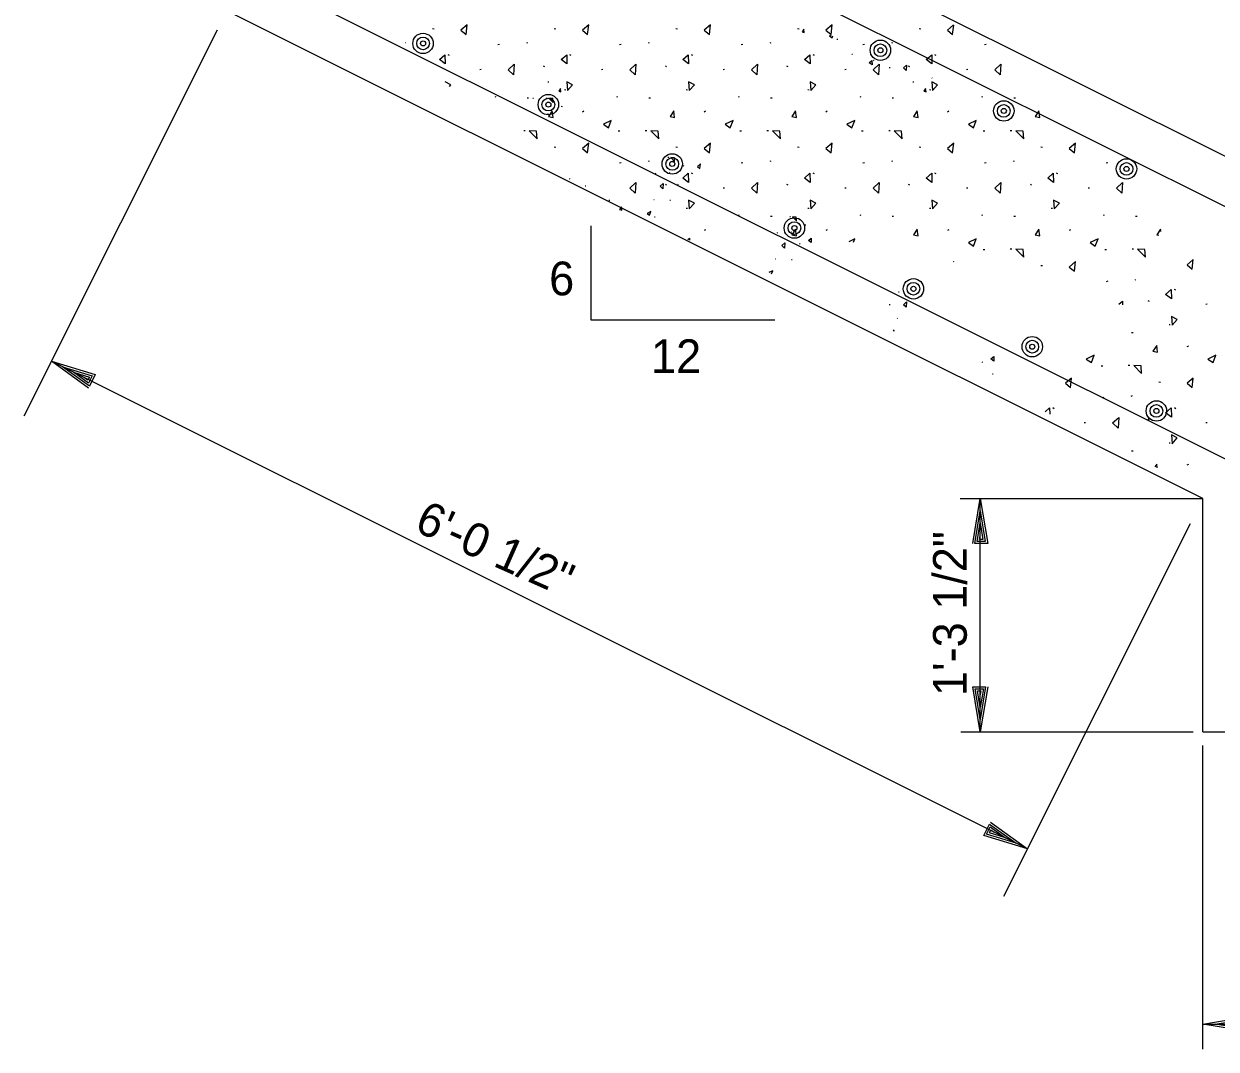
# Model space of a CAD drawing. Extents: x 6 to 106, y 3 to 74.
# Drawn here: x 75.94 to 89.14, y 24.57 to 35.93 of the extents above; entities that cross this region are included whole.
import ezdxf

# ---------------------------------------------------------------- set-up
doc = ezdxf.new("R2010")
doc.units = 0
for name, color, linetype in [('Level 22', 7, 'Continuous'), ('Level 25', 7, 'Continuous'), ('Level 44', 7, 'Continuous'), ('Level 50', 7, 'Continuous')]:
    doc.layers.add(name, color=color, linetype=linetype)

msp = doc.modelspace()

# ---------------------------------------------------------------- linework, layer by layer
at = {"layer": 'Level 22'}
for p, q in [((92.955, 32.603), (79.753, 39.204)), ((94.265, 31.389), (80.275, 38.384)), ((88.991, 30.672), (78.188, 36.074)), ((90.607, 30.423), (79.157, 36.148)), ((78.081, 35.86), (75.942, 31.582)), ((82.222, 32.645), (82.222, 33.692)), ((84.255, 32.645), (82.222, 32.645)), ((87.05, 26.791), (76.247, 32.192)), ((86.305, 30.672), (88.991, 30.672)), ((88.849, 30.389), (86.786, 26.264)), ((86.311, 28.086), (88.883, 28.086)), ((88.991, 24.85), (96.991, 24.85))]:
    msp.add_line(p, q, dxfattribs=at)
at = {"layer": 'Level 25'}
for p, q in [((86.527, 28.086), (86.527, 30.672)), ((88.991, 28.086), (88.991, 30.672)), ((88.991, 28.086), (96.991, 28.086)), ((88.991, 24.572), (88.991, 27.935))]:
    msp.add_line(p, q, dxfattribs=at)
at = {"layer": 'Level 44'}
for p, q in [((80.483, 35.87), (80.466, 35.873)), ((81.83, 35.87), (81.813, 35.873)), ((83.177, 35.87), (83.159, 35.873)), ((84.523, 35.87), (84.506, 35.873)), ((85.87, 35.87), (85.853, 35.873)), ((80.17, 35.719), (80.165, 35.717)), ((81.206, 35.701), (81.188, 35.696)), ((81.517, 35.719), (81.504, 35.714)), ((82.553, 35.701), (82.535, 35.696)), ((82.864, 35.719), (82.851, 35.714)), ((83.9, 35.701), (83.882, 35.696)), ((84.21, 35.719), (84.197, 35.714)), ((84.95, 35.756), (84.941, 35.756)), ((85.246, 35.701), (85.228, 35.696)), ((85.557, 35.719), (85.544, 35.714)), ((86.593, 35.701), (86.575, 35.696)), ((80.653, 35.578), (80.638, 35.587)), ((82, 35.578), (81.985, 35.587)), ((83.346, 35.578), (83.331, 35.587)), ((84.693, 35.578), (84.678, 35.587)), ((85.113, 35.59), (85.106, 35.588)), ((85.354, 35.52), (85.347, 35.524)), ((86.04, 35.578), (86.025, 35.587)), ((81.002, 35.422), (80.988, 35.421)), ((81.709, 35.454), (81.695, 35.461)), ((82.349, 35.422), (82.334, 35.421)), ((83.056, 35.454), (83.042, 35.461)), ((83.696, 35.422), (83.681, 35.421)), ((84.403, 35.454), (84.388, 35.461)), ((85.042, 35.422), (85.028, 35.421)), ((85.529, 35.442), (85.521, 35.441)), ((85.749, 35.454), (85.735, 35.461)), ((86.389, 35.422), (86.374, 35.421)), ((81.752, 35.284), (81.743, 35.284)), ((85.792, 35.284), (85.783, 35.284)), ((85.997, 35.328), (85.991, 35.329)), ((81.171, 35.117), (81.157, 35.119)), ((81.529, 35.106), (81.511, 35.106)), ((81.733, 35.103), (81.724, 35.103)), ((81.94, 35.195), (81.926, 35.196)), ((82.517, 35.117), (82.504, 35.119)), ((82.876, 35.106), (82.858, 35.106)), ((83.286, 35.195), (83.273, 35.196)), ((83.864, 35.117), (83.851, 35.119)), ((84.223, 35.106), (84.205, 35.106)), ((84.633, 35.195), (84.62, 35.196)), ((85.211, 35.117), (85.197, 35.119)), ((85.569, 35.106), (85.551, 35.106)), ((85.98, 35.195), (85.966, 35.196)), ((86.557, 35.117), (86.544, 35.119)), ((86.916, 35.106), (86.898, 35.106)), ((81.584, 35.1), (81.575, 35.1)), ((81.903, 35.01), (81.894, 35.012)), ((81.746, 34.935), (81.74, 34.932)), ((82.14, 34.96), (82.124, 34.952)), ((83.487, 34.96), (83.471, 34.952)), ((84.833, 34.96), (84.817, 34.952)), ((86.18, 34.96), (86.164, 34.952)), ((81.491, 34.745), (81.474, 34.745)), ((82.539, 34.739), (82.521, 34.739)), ((82.837, 34.745), (82.82, 34.745)), ((83.885, 34.739), (83.867, 34.739)), ((84.184, 34.745), (84.167, 34.745)), ((85.232, 34.739), (85.214, 34.739)), ((85.531, 34.745), (85.514, 34.745)), ((86.579, 34.739), (86.561, 34.739)), ((86.877, 34.745), (86.86, 34.745)), ((81.83, 34.559), (81.813, 34.562)), ((83.08, 34.447), (83.071, 34.447)), ((83.177, 34.559), (83.159, 34.562)), ((84.523, 34.559), (84.506, 34.562)), ((85.87, 34.559), (85.853, 34.562)), ((87.217, 34.559), (87.199, 34.562)), ((82.553, 34.39), (82.535, 34.385)), ((82.864, 34.408), (82.851, 34.403)), ((83.249, 34.354), (83.241, 34.356)), ((83.9, 34.39), (83.882, 34.385)), ((84.21, 34.408), (84.197, 34.403)), ((85.246, 34.39), (85.228, 34.385)), ((85.557, 34.408), (85.544, 34.403)), ((86.593, 34.39), (86.575, 34.385)), ((86.904, 34.408), (86.891, 34.403)), ((87.94, 34.39), (87.922, 34.385)), ((81.987, 34.208), (81.98, 34.213)), ((82.937, 34.27), (82.928, 34.267)), ((83.093, 34.279), (83.086, 34.276)), ((83.346, 34.266), (83.331, 34.275)), ((84.693, 34.266), (84.678, 34.275)), ((86.04, 34.266), (86.025, 34.275)), ((87.386, 34.266), (87.371, 34.275)), ((82.162, 34.13), (82.155, 34.129)), ((83.056, 34.142), (83.042, 34.149)), ((83.189, 34.146), (83.182, 34.149)), ((83.696, 34.11), (83.681, 34.109)), ((84.403, 34.142), (84.388, 34.149)), ((85.042, 34.11), (85.028, 34.109)), ((85.749, 34.142), (85.735, 34.149)), ((86.389, 34.11), (86.374, 34.109)), ((87.096, 34.142), (87.082, 34.149)), ((87.736, 34.11), (87.721, 34.109)), ((82.426, 33.972), (82.417, 33.972)), ((82.92, 33.978), (82.913, 33.979)), ((83.099, 33.972), (83.09, 33.972)), ((82.93, 33.788), (82.921, 33.788)), ((83.286, 33.883), (83.273, 33.884)), ((83.864, 33.805), (83.851, 33.808)), ((84.223, 33.794), (84.205, 33.794)), ((84.426, 33.792), (84.418, 33.792)), ((84.633, 33.883), (84.62, 33.884)), ((85.211, 33.805), (85.197, 33.808)), ((85.569, 33.794), (85.551, 33.794)), ((85.98, 33.883), (85.966, 33.884)), ((86.557, 33.805), (86.544, 33.808)), ((86.916, 33.794), (86.898, 33.794)), ((87.326, 33.883), (87.313, 33.884)), ((87.904, 33.805), (87.891, 33.808)), ((88.263, 33.794), (88.245, 33.794)), ((84.596, 33.698), (84.587, 33.7)), ((83.093, 33.623), (83.091, 33.622)), ((83.487, 33.648), (83.473, 33.641)), ((84.284, 33.614), (84.275, 33.611)), ((84.439, 33.623), (84.433, 33.62)), ((84.833, 33.648), (84.817, 33.64)), ((86.18, 33.648), (86.164, 33.64)), ((87.527, 33.648), (87.511, 33.64)), ((84.536, 33.49), (84.528, 33.494)), ((86.579, 33.427), (86.561, 33.427)), ((86.877, 33.433), (86.86, 33.433)), ((87.925, 33.427), (87.907, 33.427)), ((88.224, 33.433), (88.207, 33.433)), ((84.266, 33.322), (84.26, 33.323)), ((84.446, 33.316), (84.437, 33.316)), ((87.217, 33.247), (87.199, 33.25)), ((87.94, 33.078), (87.922, 33.073)), ((88.246, 33.094), (88.237, 33.091)), ((85.631, 32.958), (85.622, 32.956)), ((85.786, 32.967), (85.78, 32.965)), ((88.4, 32.854), (88.386, 32.86)), ((88.691, 32.978), (88.676, 32.987)), ((85.529, 32.818), (85.521, 32.818)), ((89.04, 32.822), (89.025, 32.82)), ((85.613, 32.666), (85.606, 32.667)), ((88.631, 32.595), (88.617, 32.596)), ((88.22, 32.505), (88.202, 32.505)), ((88.831, 32.36), (88.815, 32.352)), ((86.556, 32.179), (86.548, 32.182)), ((87.883, 32.138), (87.865, 32.138)), ((88.182, 32.145), (88.165, 32.145)), ((86.671, 32.049), (86.664, 32.05)), ((88.521, 31.958), (88.504, 31.961)), ((88.208, 31.807), (88.195, 31.802)), ((87.344, 31.666), (87.329, 31.675)), ((87.897, 31.789), (87.879, 31.784)), ((88.691, 31.666), (88.676, 31.675)), ((88.4, 31.542), (88.386, 31.549)), ((87.693, 31.51), (87.679, 31.509)), ((89.04, 31.51), (89.025, 31.509)), ((88.631, 31.283), (88.617, 31.284)), ((88.22, 31.194), (88.202, 31.194)), ((88.831, 31.048), (88.815, 31.04))]:
    msp.add_line(p, q, dxfattribs=at)
for points in [[(80.847, 35.918), (80.779, 35.859), (80.836, 35.811)], [(82.194, 35.918), (82.126, 35.859), (82.182, 35.811)], [(83.541, 35.918), (83.472, 35.859), (83.529, 35.811)], [(84.887, 35.918), (84.819, 35.859), (84.876, 35.811)], [(84.58, 35.833), (84.576, 35.869), (84.555, 35.839)], [(80.606, 35.484), (80.542, 35.532), (80.603, 35.586)], [(81.952, 35.484), (81.888, 35.532), (81.95, 35.586)], [(83.299, 35.484), (83.235, 35.532), (83.296, 35.586)], [(84.646, 35.484), (84.582, 35.532), (84.643, 35.586)], [(85.33, 35.473), (85.298, 35.497), (85.329, 35.524)], [(85.992, 35.484), (85.928, 35.532), (85.99, 35.586)], [(81.363, 35.363), (81.301, 35.42), (81.369, 35.481)], [(82.709, 35.363), (82.648, 35.42), (82.716, 35.481)], [(84.056, 35.363), (83.994, 35.42), (84.063, 35.481)], [(85.403, 35.363), (85.341, 35.42), (85.409, 35.481)], [(85.709, 35.412), (85.678, 35.441), (85.712, 35.471)], [(86.749, 35.363), (86.688, 35.42), (86.756, 35.481)], [(81.959, 35.19), (82.016, 35.254), (81.952, 35.288)], [(83.306, 35.19), (83.363, 35.254), (83.299, 35.288)], [(84.652, 35.19), (84.709, 35.254), (84.646, 35.288)], [(85.999, 35.19), (86.056, 35.254), (85.992, 35.288)], [(81.795, 35.101), (81.755, 35.103), (81.799, 35.059)], [(81.887, 35.177), (81.882, 35.213), (81.862, 35.183)], [(85.927, 35.177), (85.922, 35.213), (85.902, 35.183)], [(81.799, 34.892), (81.789, 34.965), (81.748, 34.904)], [(82.413, 34.778), (82.444, 34.859), (82.356, 34.816)], [(83.145, 34.892), (83.136, 34.965), (83.095, 34.904)], [(83.759, 34.778), (83.791, 34.859), (83.703, 34.816)], [(84.492, 34.892), (84.483, 34.965), (84.442, 34.904)], [(85.106, 34.778), (85.138, 34.859), (85.049, 34.816)], [(85.839, 34.892), (85.829, 34.965), (85.788, 34.904)], [(86.453, 34.778), (86.484, 34.859), (86.396, 34.816)], [(87.185, 34.892), (87.176, 34.965), (87.135, 34.904)], [(81.616, 34.741), (81.536, 34.745), (81.622, 34.656)], [(82.962, 34.741), (82.882, 34.745), (82.969, 34.656)], [(84.309, 34.741), (84.229, 34.745), (84.316, 34.656)], [(85.656, 34.741), (85.576, 34.745), (85.662, 34.656)], [(87.002, 34.741), (86.922, 34.745), (87.009, 34.656)], [(82.194, 34.607), (82.126, 34.547), (82.182, 34.499)], [(83.541, 34.607), (83.472, 34.547), (83.529, 34.499)], [(84.887, 34.607), (84.819, 34.547), (84.876, 34.499)], [(86.234, 34.607), (86.166, 34.547), (86.222, 34.499)], [(87.581, 34.607), (87.512, 34.547), (87.569, 34.499)], [(83.142, 34.445), (83.102, 34.447), (83.145, 34.403)], [(83.431, 34.378), (83.397, 34.348), (83.425, 34.325)], [(83.299, 34.172), (83.235, 34.22), (83.296, 34.275)], [(84.646, 34.172), (84.582, 34.22), (84.643, 34.275)], [(85.992, 34.172), (85.928, 34.22), (85.99, 34.275)], [(87.339, 34.172), (87.275, 34.22), (87.336, 34.275)], [(82.709, 34.052), (82.648, 34.109), (82.716, 34.17)], [(83.016, 34.101), (82.985, 34.129), (83.019, 34.16)], [(84.056, 34.052), (83.994, 34.109), (84.063, 34.17)], [(85.403, 34.052), (85.341, 34.109), (85.409, 34.17)], [(86.749, 34.052), (86.688, 34.109), (86.756, 34.17)], [(88.096, 34.052), (88.034, 34.109), (88.103, 34.17)], [(83.306, 33.879), (83.363, 33.943), (83.299, 33.977)], [(84.652, 33.879), (84.709, 33.943), (84.646, 33.977)], [(85.999, 33.879), (86.056, 33.943), (85.992, 33.977)], [(87.346, 33.879), (87.403, 33.943), (87.339, 33.977)], [(82.56, 33.865), (82.556, 33.902), (82.535, 33.871)], [(82.867, 33.808), (82.883, 33.849), (82.839, 33.827)], [(84.489, 33.789), (84.449, 33.792), (84.492, 33.747)], [(84.492, 33.581), (84.483, 33.654), (84.442, 33.593)], [(85.839, 33.581), (85.829, 33.654), (85.788, 33.593)], [(87.185, 33.581), (87.176, 33.654), (87.135, 33.593)], [(84.657, 33.505), (84.625, 33.529), (84.656, 33.556)], [(86.453, 33.466), (86.484, 33.548), (86.396, 33.505)], [(87.799, 33.466), (87.831, 33.548), (87.743, 33.505)], [(84.362, 33.445), (84.331, 33.473), (84.366, 33.504)], [(87.002, 33.429), (86.922, 33.433), (87.009, 33.345)], [(88.349, 33.429), (88.269, 33.433), (88.356, 33.345)], [(87.581, 33.295), (87.512, 33.235), (87.569, 33.188)], [(88.885, 33.318), (88.817, 33.258), (88.873, 33.211)], [(88.643, 32.883), (88.579, 32.932), (88.641, 32.986)], [(85.709, 32.789), (85.678, 32.818), (85.712, 32.848)], [(88.65, 32.59), (88.707, 32.654), (88.643, 32.688)], [(88.49, 32.292), (88.48, 32.365), (88.439, 32.304)], [(86.677, 32.193), (86.645, 32.218), (86.676, 32.245)], [(87.757, 32.177), (87.789, 32.259), (87.7, 32.216)], [(89.104, 32.177), (89.135, 32.259), (89.047, 32.216)], [(88.307, 32.14), (88.227, 32.145), (88.313, 32.056)], [(87.538, 32.006), (87.47, 31.947), (87.527, 31.899)], [(88.885, 32.006), (88.817, 31.947), (88.873, 31.899)], [(88.643, 31.572), (88.579, 31.62), (88.641, 31.674)], [(88.054, 31.451), (87.992, 31.508), (88.06, 31.569)], [(88.65, 31.278), (88.707, 31.342), (88.643, 31.376)]]:
    msp.add_lwpolyline(points, close=True, dxfattribs=at)
for points in [[(86.232, 35.916), (86.166, 35.859), (86.222, 35.811), (86.234, 35.915)], [(84.877, 35.804), (84.859, 35.795), (84.887, 35.775)], [(84.887, 35.775), (84.896, 35.797)], [(80.654, 35.236), (80.669, 35.254), (80.606, 35.288), (80.606, 35.283)], [(88.526, 33.63), (88.523, 33.654), (88.482, 33.593), (88.503, 33.587)], [(83.291, 33.541), (83.309, 33.556), (83.31, 33.533)], [(85.124, 33.511), (85.138, 33.548), (85.072, 33.515)], [(86.234, 33.295), (86.233, 33.293)], [(86.234, 33.293), (86.234, 33.295)], [(84.217, 33.161), (84.23, 33.193), (84.189, 33.173)], [(88.063, 32.822), (88.103, 32.858), (88.1, 32.816)], [(85.572, 32.526), (85.576, 32.537), (85.562, 32.53)], [(87.245, 31.631), (87.294, 31.674), (87.296, 31.606)], [(88.486, 31.01), (88.48, 31.053), (88.46, 31.023)]]:
    msp.add_lwpolyline(points, dxfattribs=at)
at = {"layer": 'Level 50'}
for p, q in [((76.247, 32.192), (76.247, 32.192)), ((76.371, 32.13), (76.371, 32.13)), ((86.527, 30.672), (86.527, 30.672)), ((86.527, 30.534), (86.527, 30.534)), ((86.527, 28.225), (86.527, 28.225)), ((86.527, 28.086), (86.527, 28.086)), ((86.926, 26.853), (86.926, 26.853)), ((86.926, 26.853), (86.926, 26.853)), ((87.05, 26.791), (87.05, 26.791)), ((87.05, 26.791), (87.05, 26.791)), ((88.991, 24.85), (88.991, 24.85)), ((89.129, 24.85), (89.129, 24.85))]:
    msp.add_line(p, q, dxfattribs=at)
for points in [[(76.656, 31.895), (76.247, 32.192), (76.73, 32.043), (76.667, 31.917), (76.371, 32.13), (76.699, 32.029), (76.658, 31.948), (76.49, 32.071), (76.668, 32.015), (76.651, 31.981), (76.614, 32.009)], [(86.444, 30.174), (86.527, 30.672), (86.61, 30.174), (86.468, 30.174), (86.527, 30.534), (86.583, 30.195), (86.492, 30.195), (86.527, 30.4), (86.556, 30.216), (86.519, 30.216), (86.527, 30.262)], [(86.61, 28.585), (86.527, 28.086), (86.444, 28.585), (86.586, 28.585), (86.527, 28.225), (86.471, 28.564), (86.562, 28.564), (86.527, 28.358), (86.498, 28.542), (86.535, 28.542), (86.527, 28.497)], [(86.641, 27.088), (87.05, 26.791), (86.567, 26.94), (86.63, 27.066), (86.926, 26.853), (86.598, 26.954), (86.638, 27.035), (86.807, 26.913), (86.629, 26.969), (86.646, 27.002), (86.683, 26.975)], [(86.641, 27.088), (87.05, 26.791), (86.567, 26.94), (86.63, 27.066), (86.926, 26.853), (86.598, 26.954), (86.638, 27.035), (86.807, 26.913), (86.629, 26.969), (86.646, 27.002), (86.683, 26.975)], [(89.489, 24.767), (88.991, 24.85), (89.489, 24.933), (89.489, 24.791), (89.129, 24.85), (89.468, 24.906), (89.468, 24.815), (89.263, 24.85), (89.447, 24.879), (89.447, 24.842), (89.401, 24.85)]]:
    msp.add_lwpolyline(points, dxfattribs=at)
for centre, radius in [((80.36, 35.712), 0.113), ((80.36, 35.712), 0.0703), ((80.36, 35.712), 0.0281), ((85.422, 35.636), 0.113), ((85.422, 35.636), 0.0703), ((85.422, 35.636), 0.0281), ((81.747, 35.034), 0.113), ((81.747, 35.034), 0.0703), ((81.747, 35.034), 0.0281), ((86.788, 34.964), 0.113), ((86.788, 34.964), 0.0703), ((86.788, 34.964), 0.0281), ((83.118, 34.377), 0.113), ((83.118, 34.377), 0.0703), ((83.118, 34.377), 0.0281), ((88.146, 34.322), 0.113), ((88.146, 34.322), 0.0703), ((88.146, 34.322), 0.0281), ((84.47, 33.667), 0.113), ((84.47, 33.667), 0.0703), ((84.47, 33.667), 0.0281), ((85.788, 32.994), 0.113), ((85.788, 32.994), 0.0703), ((85.788, 32.994), 0.0281), ((87.103, 32.353), 0.113), ((87.103, 32.353), 0.0703), ((87.103, 32.353), 0.0281), ((88.477, 31.641), 0.113), ((88.477, 31.641), 0.0703), ((88.477, 31.641), 0.0281)]:
    msp.add_circle(centre, radius, dxfattribs=at)

# ---------------------------------------------------------------- texts
at = {"layer": 'Level 22'}
for s, height, p in [('6', 0.373, (81.756, 32.922)), ('12', 0.3733, (82.883, 32.061))]:
    msp.add_text(s, height=height, dxfattribs=at).set_placement(p)
for s, rotation, p in [('6\'-0 1/2"', 336, (80.25, 30.318)), ('1\'-3 1/2"', 90, (86.378, 28.483))]:
    msp.add_text(s, height=0.3733, rotation=rotation, dxfattribs=at).set_placement(p)

doc.saveas('drawing.dxf')
